(* Logix 5000 project; controller TimeSyncExample vendor 1 type 14 code 77 rev 19.11; software revision 19.01 *)

TASK MainTask (continuous, watchdog 500 ms) : MainProgram

MODULES
   Controller : vendor 1 type 14 code 77 (CompactLogixL32EController 0, rev 19.11)
      LocalENB : 1769-L32E Ethernet Port (CompactLogixL32Ethernet 1, rev 19.11)
         TSM01 : ETHERNET-MODULE (Ethernet 192.168.1.235, rev 1.1, Output RPI 200 ms)
      Local : CompactBus (CompactVirtualAdapter 3, rev 19.11)
END_MODULES

TYPE AparianTimeSyncAccuracy :
STRUCT
   PDOP : REAL;
   HDOP : REAL;
   VDOP : REAL;
   LatitudeError : REAL;
   LongtitudeError : REAL;
   AltitudeError : REAL;
END_STRUCT
END_TYPE

TYPE AparianTimeSyncDateTime :
STRUCT
   UTC : LINT;
   Year : INT;
   Month : SINT;
   Day : SINT;
   Hour : SINT;
   Minute : SINT;
   Second : SINT;
   Nanosecond : DINT;
END_STRUCT
END_TYPE

TYPE AparianTimeSyncInput :
STRUCT
   Instance : STRING;
   Status : AparianTimeSyncStatusR02;
   InterferenceIndication : REAL;
   SatelliteCount : SINT;
   DateTime : AparianTimeSyncDateTime;
   Velocity : AparianTimeSyncVelocity;
   Position : AparianTimeSyncPosition;
   Odometer : AparianTimeSyncOdometer;
   Accuracy : AparianTimeSyncAccuracy;
END_STRUCT
END_TYPE

TYPE AparianTimeSyncOdometer :
STRUCT
   DistanceSinceReset : DINT;
   DistanceTotal : DINT;
   DistanceAccuracy : DINT;
END_STRUCT
END_TYPE

TYPE AparianTimeSyncOutput :
STRUCT
   ReferenceLatitude : REAL;
   ReferenceLongtitude : REAL;
   ReferenceAltitude : REAL;
END_STRUCT
END_TYPE

TYPE AparianTimeSyncPosition :
STRUCT
   Latitude : REAL;
   Longtitude : REAL;
   Altitude : REAL;
   ReferenceLatitude : REAL;
   ReferenceLongtitude : REAL;
   ReferenceAltitude : REAL;
   RelativeLatitude : REAL;
   RelativeLongtitude : REAL;
   RelativeAltitude : REAL;
   RelativeNorth : REAL;
   RelativeEast : REAL;
END_STRUCT
END_TYPE

TYPE AparianTimeSyncStatusR02 :
STRUCT
   ConfigurationValid : BOOL;
   PTPEnabled : BOOL;
   NTPEnabled : BOOL;
   AntennaShort : BOOL;
   Fix2D : BOOL;
   Fix3D : BOOL;
   FixAutonomous : BOOL;
   FixDifferential : BOOL;
   NTPSource1Connected : BOOL;
   NTPSource2Connected : BOOL;
END_STRUCT
END_TYPE

TYPE AparianTimeSyncVelocity :
STRUCT
   TrueCourseOverGround : REAL;
   SpeedOverGroundKnots : REAL;
   SpeedOverGroundKmh : REAL;
END_STRUCT
END_TYPE

VAR_GLOBAL   (* controller tags *)
   ResetOdometer : MESSAGE;
        MessageParameters(ServiceCode := 16#0076, ...)
   TimeSyncEnableCPUSet : BOOL := 1;
   TimeSyncIntervalTimer : TIMER := (PRE := 5000);
   TimeSyncResetOdometer : BOOL;
   TSM01Input : AparianTimeSyncInput := (Instance := 'TimeSync1', Status.ConfigurationValid := 1, Status.PTPEnabled := 1, Status.NTPEnabled := 1, Status.Fix3D := 1, Status.FixAutonomous := 1, InterferenceIndication := 36.078434, SatelliteCount := 7, DateTime.UTC := 1526282416139059, DateTime.Year := 2018, DateTime.Month := 5, DateTime.Day := 14, DateTime.Hour := 7, DateTime.Minute := 20, DateTime.Second := 15, DateTime.Nanosecond := 139059087, Velocity.SpeedOverGroundKnots := 1.189, Velocity.SpeedOverGroundKmh := 2.203, Position.Latitude := -26.10623, Position.Longtitude := 28.002247, Position.Altitude := 1637.8999, Position.RelativeLatitude := -26.106228, Position.RelativeLongtitude := 28.002247, Position.RelativeAltitude := 1637.9, Position.RelativeNorth := 2647174.0, Position.RelativeEast := -3219453.8, Odometer.DistanceSinceReset := 10701, Odometer.DistanceTotal := 10701, Odometer.DistanceAccuracy := 233, Accuracy.PDOP := 2.78, Accuracy.HDOP := 1.26, Accuracy.VDOP := 2.47, Accuracy.LatitudeError := 6.2, Accuracy.LongtitudeError := 3.9, Accuracy.AltitudeError := 11.0);
   TSM01Output : AparianTimeSyncOutput;
END_VAR

PROGRAM MainProgram   (* main routine MainRoutine *)

ROUTINE MainRoutine   (* ladder *)
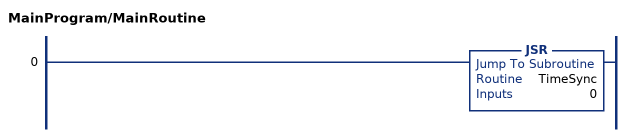
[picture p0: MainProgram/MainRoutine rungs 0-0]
   0: JSR(TimeSync,0);
END_ROUTINE

ROUTINE TimeSync   (* ladder *)
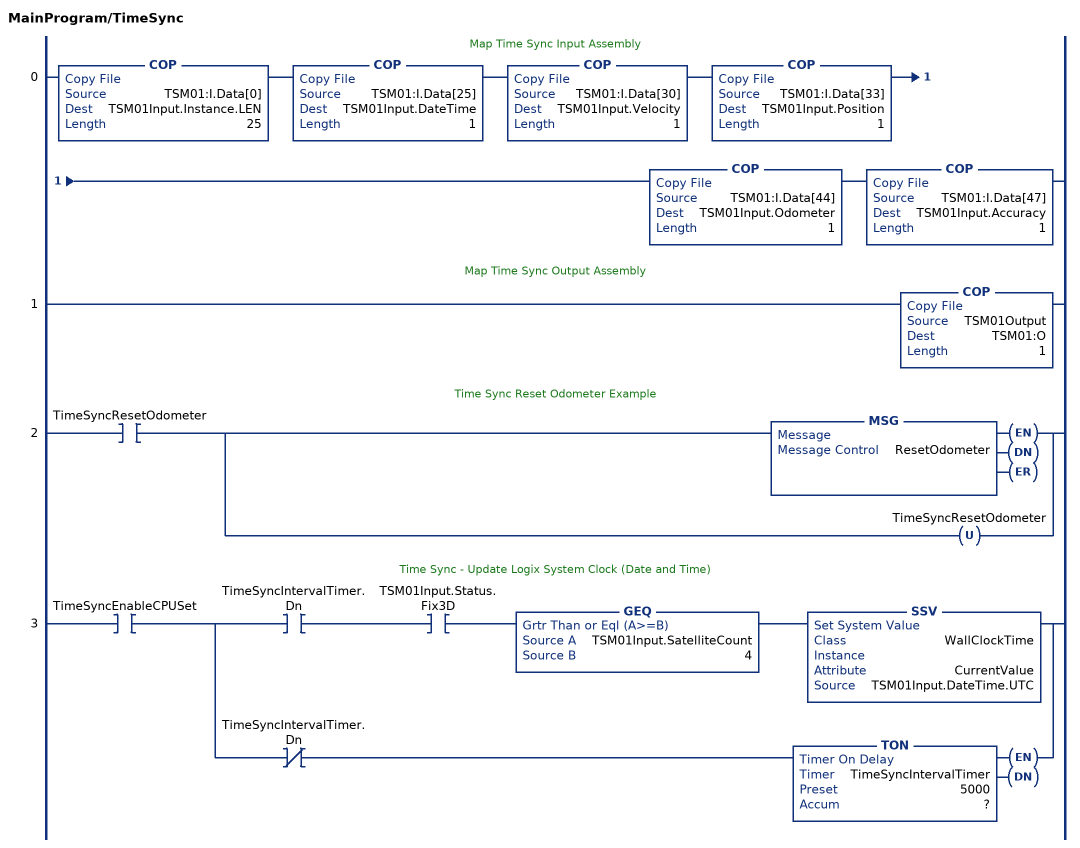
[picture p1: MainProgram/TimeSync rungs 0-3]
   // Map Time Sync Input Assembly
   0: COP(TSM01:I.Data[0],TSM01Input.Instance.LEN,25)COP(TSM01:I.Data[25],TSM01Input.DateTime,1)COP(TSM01:I.Data[30],TSM01Input.Velocity,1)COP(TSM01:I.Data[33],TSM01Input.Position,1)COP(TSM01:I.Data[44],TSM01Input.Odometer,1)COP(TSM01:I.Data[47],TSM01Input.Accuracy,1);
   // Map Time Sync Output Assembly
   1: COP(TSM01Output,TSM01:O,1);
   // Time Sync Reset Odometer Example
   2: XIC(TimeSyncResetOdometer)[MSG(ResetOdometer) ,OTU(TimeSyncResetOdometer) ];
   // Time Sync - Update Logix System Clock (Date and Time)
   3: XIC(TimeSyncEnableCPUSet)[XIC(TimeSyncIntervalTimer.Dn) XIC(TSM01Input.Status.Fix3D) GEQ(TSM01Input.SatelliteCount,4) SSV(WallClockTime,,CurrentValue,TSM01Input.DateTime.UTC) ,XIO(TimeSyncIntervalTimer.Dn) TON(TimeSyncIntervalTimer,?,?) ];
END_ROUTINE
END_PROGRAM
